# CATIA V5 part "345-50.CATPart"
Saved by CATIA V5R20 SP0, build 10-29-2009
Part number: 345-50
Definition: NONE
Nomenclature: 345-50
Source: Unknown
Description: 345-50
Bounding box of the stored display mesh (mm): x 0 to 100, y -51.5 to 51.5, z -51.5 to 51.5
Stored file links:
  C:\Users\Utente\Desktop\IO LAVORO\3D X SITO CF\X SITO\345-346\345-50.CATPart
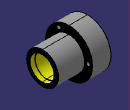
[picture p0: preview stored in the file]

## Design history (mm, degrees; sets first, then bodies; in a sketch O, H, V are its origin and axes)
Body1 "345-50" (main body)
  Solid1: solid without history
